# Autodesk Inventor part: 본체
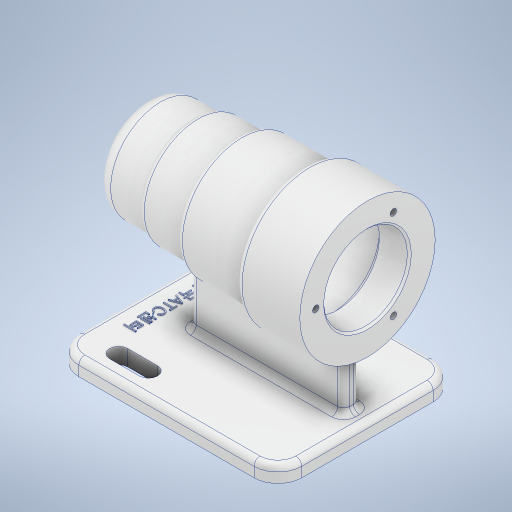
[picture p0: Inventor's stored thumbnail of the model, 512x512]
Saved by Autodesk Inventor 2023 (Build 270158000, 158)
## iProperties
Created: 2022-07
Part Number: 본체
Material: 알루미늄 6061
Document SubType Name: Modeling
Designer: owner
Density: 2.7 g/cm^3
Appearance: 알루미늄 - 평지
Mass: 663.189 g
Surface Area: 695.07 cm^2
Volume: 245.626 cm^3
Author: owner
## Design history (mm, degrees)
sketch "스케치1"
  geometry: L1 (-56, 70)-(56, 70); L2 (-56, 70)-(-56, 95); L3 (-56, 95)-(-32, 95); L4 (-32, 95)-(-32, 97); L5 (-32, 97)-(-10, 97); L6 (-10, 97)-(-10, 100); L7 (-10, 100)-(24, 100); L8 (24, 100)-(24, 104); L9 (24, 104)-(56, 104); L10 (56, 104)-(56, 70); 2 further points
  constraints: 20 end point, 6 perpendicular, 3 vertical, 1 horizontal, 1 midpoint, 1 vertical alignment
  dimensions: "d0" = 24 distance between parallel lines of L4 L2; "d1" = 46 distance between parallel lines of L6 L2; "d2" = 80 distance between parallel lines of L8 L2; "d3" = 112 distance between parallel lines of L10 L2; "d4" = 68 diameter of L9 L1; "d5" = 60 diameter of L7 L1; "d6" = 54 diameter of L5 L1; "d7" = 50 diameter of L3 L1; "d8" = 70 distance from line of point (0, 0) L1
revolve "회전1" sketch "스케치1" stored, may be unused: angle "d9" = 90 deg
sketch "스케치2"
  geometry: L1 (-56, 45)-(-56, 95) reference; L2 (56, 36)-(56, 104) reference; L3 (-56, 70)-(56, 70); L4 (-50, 70)-(-50, 77.5); L5 (-47, 80.5)-(-47, 80.5); L6 (-47, 80.5)-(-47, 85.7); L7 (-46.7, 86)-(-43, 86); L8 (-43, 86)-(-43, 87.2); L9 (-42.7, 87.5)-(-25, 87.5); L10 (-25, 87.5)-(-25, 90.7); L11 (-24.7, 91)-(-13, 91); L12 (-13, 91)-(-13, 91); L13 (-10, 94)-(38, 94); L14 (41, 91)-(41, 91); L15 (41, 91)-(56, 91); A1 r 0.3 centre (-46.7, 85.7) between (-46.7, 86) and (-47, 85.7); A2 r 0.3 centre (-42.7, 87.2) between (-42.7, 87.5) and (-43, 87.2); A3 r 0.3 centre (-24.7, 90.7) between (-24.7, 91) and (-25, 90.7); A4 r 3 centre (-47, 77.5) between (-47, 80.5) and (-50, 77.5); A5 r 3 centre (-10, 91) between (-10, 94) and (-13, 91); A6 r 3 centre (38, 91) between (41, 91) and (38, 94); 10 further points
  constraints: 26 end point, 14 point on line, 12 point on circle, 12 tangent, 9 perpendicular, 6 centre point, 4 equal radius, 2 midpoint, 2 vertical, 1 horizontal
  dimensions: "d10" = 15 distance between parallel lines of L14 L2; "d11" = 42 diameter of L15 L3; "d12" = 54 distance between parallel lines of L14 L12; "d13" = 48 diameter of L13 L3; "d14" = 12 distance between parallel lines of L12 L10; "d15" = 42 diameter of L11 L3; "d16" = 18 distance between parallel lines of L8 L10; "d17" = 35 diameter of L9 L3; "d18" = 32 diameter of L7 L3; "d19" = 4 distance between parallel lines of L8 L6; "d20" = 3 distance between parallel lines of L6 L4; "d21" = 21 diameter of L5 L3; "d23" = 0.3 radius of A1; "d24" = 3 radius of A4
revolve "회전2" sketch "스케치2" stored, may be unused: angle "d22" = 90 deg
sketch "스케치3"
  geometry: L1 (-56, 45)-(56, 45); L2 (56, 45)-(56, -45); L3 (56, -45)-(-56, -45); L4 (-56, -45)-(-56, 45); L5 (-56, 45)-(56, -45); L6 (56, 45)-(-56, -45); L7 (56, 0)-(-56, 0); L8 (56, -33)-(-56, -33); L9 (56, 33)-(-56, 33); L10 (36, 33)-(21, 33); L11 (36, 37.5)-(21, 37.5); L12 (21, 28.5)-(36, 28.5); L13 (0, 45)-(0, -45); L14 (21, -28.5)-(36, -28.5); L15 (36, -37.5)-(21, -37.5); L16 (-4, 33)-(-17.708, 33); L17 (-4, 37.5)-(-17.708, 37.5); L18 (-17.708, 28.5)-(-4, 28.5); L19 (-17.708, -28.5)-(-4, -28.5); L20 (-4, -37.5)-(-17.708, -37.5); A1 r 4.5 centre (36, 33) between (36, 28.5) and (36, 37.5); A2 r 4.5 centre (21, 33) between (21, 37.5) and (21, 28.5); A3 r 4.5 centre (21, -33) between (21, -28.5) and (21, -37.5); A4 r 4.5 centre (36, -33) between (36, -37.5) and (36, -28.5); A5 r 4.5 centre (-4, 33) between (-4, 28.5) and (-4, 37.5); A6 r 4.5 centre (-17.708, 33) between (-17.708, 37.5) and (-17.708, 28.5); A7 r 4.5 centre (-17.708, -33) between (-17.708, -28.5) and (-17.708, -37.5); A8 r 4.5 centre (-4, -33) between (-4, -37.5) and (-4, -28.5); 3 further points
  constraints: 44 end point, 16 point on circle, 12 symmetric about line, 8 centre point, 8 midpoint, 8 point on line, 8 tangent, 6 parallel, 3 perpendicular, 1 collinear, 1 horizontal, 1 horizontal alignment, 4 other
  dimensions: "d25" = 112 distance of L2.end L3.end; "d26" = 90 distance of L1.end L2.end; "d27" = 33 distance between parallel lines of L7 L8; "d28" = 33 distance between parallel lines of L7 L9; "d29" = 9 distance between parallel lines of L11 L12; "d30" = 20 distance from line of L11.start L2; "d31" = 15 distance of L11.end L11.start; "d69" = 25 distance of L17.start L11.end; "d71" = 9 distance between parallel lines of L18 L17
extrude "돌출1" join sketch "스케치3" distance "d32" = 8; taper "d33" = 0 deg
sketch "스케치4"
  geometry: L1 (-29, 4)-(48, 4); L2 (48, 4)-(48, -4); L3 (48, -4)-(-29, -4); L4 (-29, -4)-(-29, 4); L5 (56, -45)-(56, 45) reference; 2 further points
  constraints: 8 end point, 2 parallel, 1 horizontal, 1 horizontal alignment, 1 midpoint, 1 perpendicular
  dimensions: "d34" = 8 distance between parallel lines of L5 L2; "d35" = 77 distance between parallel lines of L4 L2; "d36" = 8 distance between parallel lines of L3 L1
extrude "돌출2" join sketch "스케치4" stored distance "d37" = 8; taper "d38" = 0 deg
sketch "스케치7" dims "d54" = 52
  geometry: C1 r 16 at (0, 0) reference; 3 further points
  constraints: 2 horizontal alignment, 1 coincident, 2 other
hole "구멍1" sketch "스케치7" at (-26, 0) diameter "d47" = 3.242; stored, may be unused: countersink angle "d51" = 90 deg, drill point angle "d53" = 118 deg; dims "d48" = 8, "d49" = 4, "d50" = 2, "d52" = 11
fillet "모깎기1" dims "d58" = 12
fillet "모깎기2" dims "d59" = 3
chamfer "모따기1" distance "d60" = 1; stored, may be unused: second distance "d61" = 2, angle "d62" = 45 deg
fillet "모깎기3" dims "d63" = 3
sketch "스케치8"
  geometry: L1 (-56, 33)-(-56, -33) reference; 3 further points
  constraints: 1 horizontal alignment, 1 midpoint, 1 other
  dimensions: "d64" = 12 distance from line of point (-44, 0) L1
feature "엠보싱1" sketch "스케치8" dims "d0" = 24, "d1" = 46, "d2" = 80, "d3" = 112, "d4" = 68, "d5" = 60, "d6" = 54, "d7" = 50, "d8" = 70, "d65" = 0.5, "d66" = 0
fillet "모깎기5" dims "d68" = 3
fillet "모깎기6" dims "d72" = 8
node "솔리드1"
pattern_circular "원형 패턴1" dims angle "d56" = 360 deg
feature "A9D066F2-1C7D-4E18-AEED-F7BC21143FA4" dims "d47" = 3.242, "d48" = 8, "d49" = 4, "d50" = 2, "d51" = 90 deg, "d52" = 11, "d53" = 118 deg
